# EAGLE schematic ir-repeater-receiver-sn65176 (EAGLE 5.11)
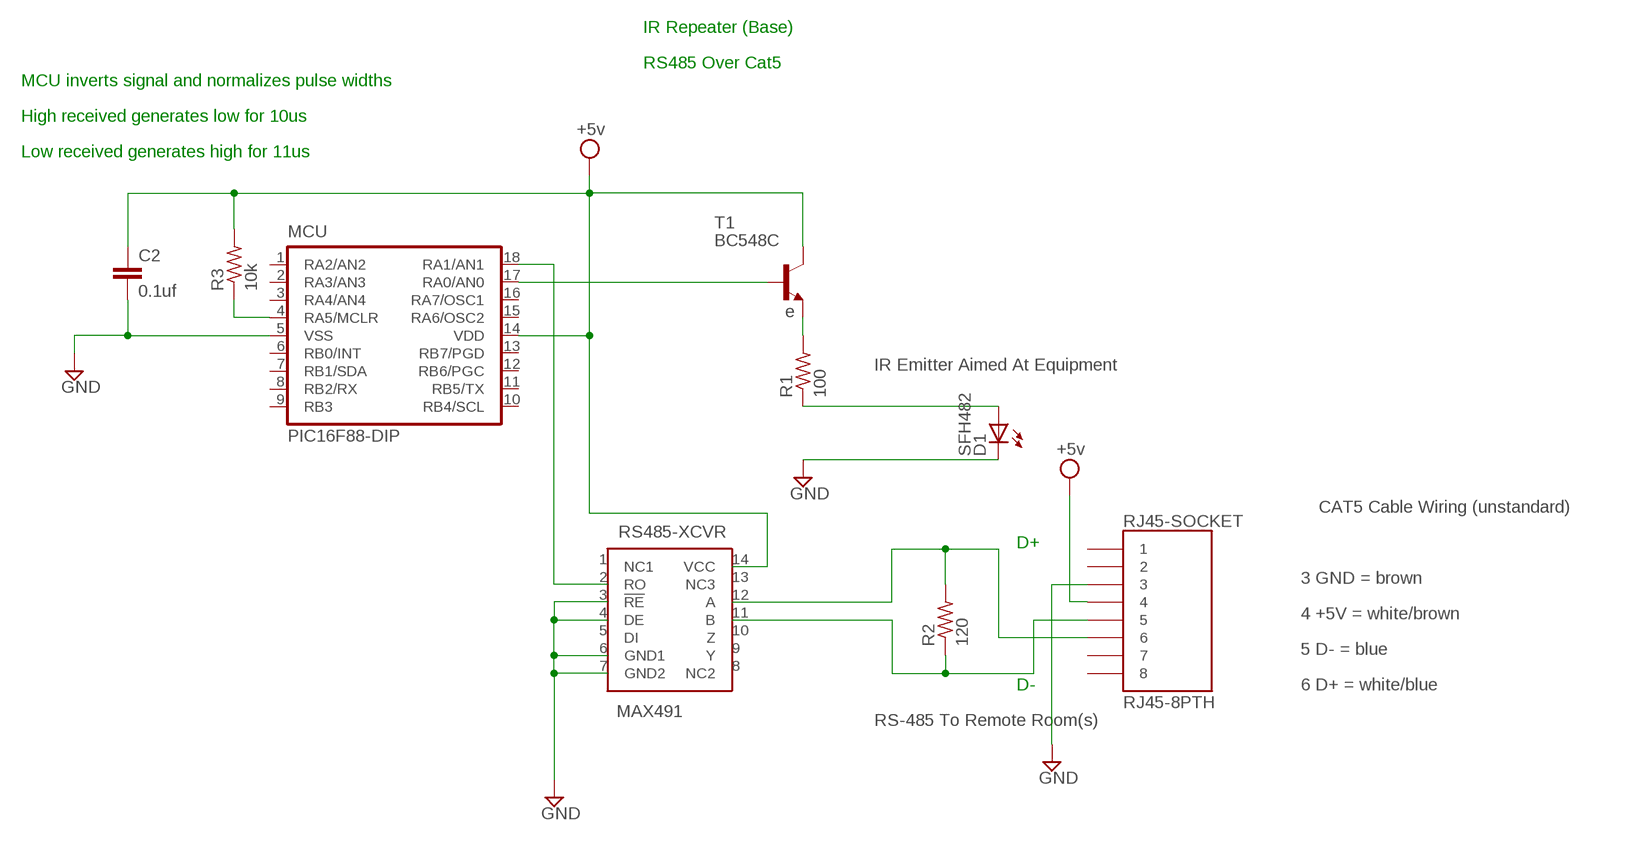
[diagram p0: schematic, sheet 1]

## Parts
C2  0.1uf  CAPPTH  [CAP-PTH-SMALL]
D1  SFH482  [SFH482]
MCU  PIC16F88-DIP  [DIL18]
R1  100  R-US_0411/15  [0411/15]
R2  120  R-US_0411/15  [0411/15]
R3  10k  R-US_0411/15  [0411/15]
RJ45-SOCKET  RJ45-8PTH  [RJ45-8]
RS485-XCVR  MAX491  [14DIP]
T1  BC548C  BC548C-NPN-TO92-EBC  [TO92-EBC]

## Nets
GND: C2.2 D1.K(C) MCU.5(VSS) RJ45-SOCKET.3 RS485-XCVR.3(!RE) RS485-XCVR.4(DE) RS485-XCVR.6(GND1) RS485-XCVR.7(GND2)
N$1: MCU.17(RA0/AN0) T1.B
N$2: D1.A R1.1
N$3: R1.2 T1.E
N$4: MCU.18(RA1/AN1) RS485-XCVR.2(RO)
N$5: MCU.4(RA5/MCLR) R3.1
N$8: R2.2 RJ45-SOCKET.6 RS485-XCVR.12(A)
N$9: R2.1 RJ45-SOCKET.5 RS485-XCVR.11(B)
VCC: C2.1 MCU.14(VDD) R3.2 RJ45-SOCKET.4 RS485-XCVR.14(VCC) T1.C ; supply symbol labelled +5v
Unconnected: MCU.1(RA2/AN2) MCU.2(RA3/AN3) MCU.3(RA4/AN4) MCU.6(RB0/INT) MCU.7(RB1/SDA) MCU.8(RB2/RX) MCU.9(RB3) MCU.10(RB4/SCL) MCU.11(RB5/TX) MCU.12(RB6/PGC) MCU.13(RB7/PGD) MCU.15(RA6/OSC2) MCU.16(RA7/OSC1) RJ45-SOCKET.1 RJ45-SOCKET.2 RJ45-SOCKET.7 RJ45-SOCKET.8 RS485-XCVR.1(NC1) RS485-XCVR.5(DI) RS485-XCVR.8(NC2) RS485-XCVR.9(Y) RS485-XCVR.10(Z) RS485-XCVR.13(NC3)

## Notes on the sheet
- IR Repeater (Base)
- RS485 Over Cat5
- MCU inverts signal and normalizes pulse widths
- High received generates low for 10us
- Low received generates high for 11us
- e
- IR Emitter Aimed At Equipment
- CAT5 Cable Wiring (unstandard)
- D+
- 3 GND = brown
- 4 +5V = white/brown
- 5 D- = blue
- D- | 6 D+ = white/blue
- RS-485 To Remote Room(s)

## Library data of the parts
C2 = SparkFun:CAP: Capacitor
D1 = led:SFH482: IR LED
MCU = SparkFun:PIC16F88-DIP
R1-R3 = resistor:R-US_: RESISTOR, American symbol
RJ45-SOCKET = SparkFun:RJ45-8: RJ45 Jack Simple RJ45, 8-pin connection - connector for common Cat5, Cat5e, and Cat6 Ethernet cables. Footprint not yet proven in production. Connector sku is PRT-00643; Breakout PCB sku is BOB-00716.
RS485-XCVR = trl:MAX491
T1 = transistor:*-NPN-: NPN Transistror BF959 corrected 2008.03.06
